(* Logix 5000 project; controller Test vendor 1 type 14 code 92 rev 32.11; software revision 32.00 *)

TASK MainTask (continuous, watchdog 500 ms) : MainProgram

MODULES
   Local : vendor 1 type 14 code 92 (ICP 0, rev 32.11)
      IN : vendor 1 type 7 code 1 (ICP 3, rev 3.2, Input RPI 20 ms)
      O : vendor 1 type 7 code 15 (ICP 2, rev 3.2, Output RPI 20 ms)
      Ethernet : 1756-ENBT (ICP 1, Ethernet 192.168.0.98, rev 6.4)
         SC10 : XS26 SC26 SC10 (Ethernet 192.168.0.128, rev 2.1, StandardDataDriven RPI 100 ms)
END_MODULES

TYPE Banner_Chain_Status_v1 :
STRUCT
   Device_Count_Mismatch : BOOL;   // 0 = False, 1 = True
   Device_Order_Mismatch : BOOL;   // 0 = False, 1 = True
   No_Diagnostics_Data_Detected : BOOL;   // 0 = False, 1 = True
   bit3 : BOOL;
   Incompatible_Device : BOOL;   // 0 = False, 1 = True
   ISD_Terminator_Missing : BOOL;   // 0 = False, 1 = True
   ISD_Actuator_Not_Taught : BOOL;   // 0 = False, 1 = True
   ISD_Wrong_Actuator : BOOL;   // 0 = False, 1 = True
   ISD_Internal_Error : BOOL;   // 0 = False, 1 = True
   ISD_Output_Fault_Detected : BOOL;   // 0 = False, 1 = True
   ISD_Chain_Change_Detected : BOOL;   // 0 = False, 1 = True
   bit11 : BOOL;
   ISD_OSSD_Status : BOOL;   // 0 = Off, 1 = ON
   bit13 : BOOL;
   bit14 : BOOL;
   bit15 : BOOL;
   bit16 : BOOL;
   bit17 : BOOL;
   bit18 : BOOL;
   bit19 : BOOL;
   bit20 : BOOL;
   bit21 : BOOL;
   bit22 : BOOL;
   bit23 : BOOL;
   bit24 : BOOL;
   bit25 : BOOL;
   bit26 : BOOL;
   bit27 : BOOL;
   bit28 : BOOL;
   bit29 : BOOL;
   bit30 : BOOL;
   bit31 : BOOL;
END_STRUCT
END_TYPE

TYPE Banner_ISD_Data_v1 :   // Tag Data for a Banner ISD Device.
STRUCT
   Safety_Input_Fault : SINT;   // System detected a fault on the safety input. Power cycle required. 1 = True, 0 = False.
   Reserved : SINT;
   Sensor_not_Paired : SINT;   // Si-RF Only. High or Unique sensor that has not been taught (not taught 1, taught 0)
   ISD_Data_Error : SINT;   // 1 = corrupted data was received by the Safety Controller, 0 = data ok.
   Wrong_Actuator : SINT;   // Si-RF sensor detects an actuator with a "received code" that does not match the "expected code" (wrong 1, correct 0).
   Marginal_Range : SINT;   // Si-RF Only. Actuator detected but is staying at the extreme end of detection range (13 to 15 mm away from sensor). 1 = True, 0 = False.
   Actuator_Detected : SINT;   // Si-RF sensor detects an actuator. Note: It does not have to be the taught actuator.
   Output_Error : SINT;   // ISD device detects an output short to voltage or ground. This starts the "switch-off timer" counter. 1= Error detected, 0 = OK.
   Input_1 : SINT;   // ISD device input 1 is on (1) or off (0)
   Input_2 : SINT;   // ISD device input 2 is on (1) or off (0)
   Local_Reset_Expected : SINT;   // An ISD device with latching feature requires a reset. 1 = reset needed. ISD Connect is always 0.
   Operating_Voltage_Warning : SINT;   // Voltage to the ISD device is at limit of specificaitons. 1 = at limit, 0 = OK.
   Operating_Voltage_Error : SINT;   // Voltage to the ISD device is above/over 30 Vdc or below/less 19.2 Vdc limit of range.
   Output_1 : SINT;   // 1 = Output On, 0 = Output Off
   Output_2 : SINT;   // 1 = Output On, 0 = Output Off
   Power_Cycle_Required : SINT;   // 1 = ISD device detects a fault. Power cycled required.
   Fault_Tolerant_Outputs : SINT;   // 1 = ISD device includes 20 minute off delay/fault delay. Always 1 for ISD E-Stop and ISD Connect.
   Local_Reset_Unit : SINT;   // 1 = ISD device includes the latch feature, 0 = device has the auto reset feature. Always 0 for ISD Connect.
   Cascadable : SINT;   // 1 = ISD device includes the cascade feature. Always 1 for ISD E-Stop and ISD Connect.
   High_Coding_Level : SINT;   // Si-RF Only. 1 = Device is High or Unique model, 0 = Low model.
   Teach_ins_Remaining : INT;   // Si-RF Only. Number of teaches remaining for Si-RF devices with high or unique coding.
   Device_Id : INT;   // ISD Device Type 1 = Si-RF. 7 for ISD E-Stop, 9 for ISD Connect.
   Range_Warning_Count : INT;   // Si-RF sensor only. Count of number of range warnings received in the last 60 minutes.
   Output_Switch_Out_Time : INT;   // Delay counter for certain output errors. 0 = inactive, 1 to 20 = remaining minutes to device lockout state. Value = 31 means Timer is Off.
   Number_of_Voltage_Errors : INT;   // 0 to 60 = Number of voltage warnings received in the last 60 seconds.
   Internal_Temperature : REAL;   // Internal temperature of device in Celsius.
   Actuator_Distance : REAL;   // The distance the actuator is from the Si-RF. Value displayed as a percentage of the Si-RF range.
   Supply_Voltage : REAL;   // Actual input voltage detected by the ISD sensor.
   Expected_Company_Name : INT;   // Fixed value of 6.
   Received_Company_Name : INT;   // Si-RF Only. Value received from Sensor. Should match Expected Company Name.
   Expected_Code : INT;   // Si-RF sensor with high or unique coding displays the actuator code taught to the sensor.
   Received_Code : INT;   // Displays actuator code detected by the Si-RF sensor.
   Internal_Error_A : DINT;
   Internal_Error_B : DINT;
END_STRUCT
END_TYPE

TYPE Banner_ISD_Devices_v1 :
STRUCT
   Device : SINT[32];   // 1 = ISD Si-RF switch, 7 = ISD E-Stop, 9 = ISD Connect
END_STRUCT
END_TYPE

TYPE Banner_ISD_Dual_Chain_Status_v1 :   // UDT that gives the overall Chain information for an ISD device.
STRUCT
   C1_Inputs : DINT;
   C2_Inputs : DINT;
   C1_On_Off : DINT;
   C2_On_Off : DINT;
   C1_Fault : DINT;
   C2_Fault : DINT;
   C1_Marginal : DINT;
   C2_Marginal : DINT;
   C1_Alert : DINT;
   C2_Alert : DINT;
   C1_Reset : DINT;
   C2_Reset : DINT;
   C1_Actuator_State : DINT;
   C2_Actuator_State : DINT;
   C1_Series_Status : Banner_Chain_Status_v1;
   C2_Series_Status : Banner_Chain_Status_v1;
END_STRUCT
END_TYPE

TYPE Banner_ISD_UDT_v1 :
STRUCT
   ISD_Request : INT;   // Set to 1 to start an ISD Request to the Safety Controller.
   ISD_Chain : INT;   // Set to a value of 1 to 2 for SC10, or 1 to 8 for XS26.
   ISD_Device : INT;   // Enter a value fo 1 to 32 to access that device during the ISD communications.
   ISD_Request_ACK : INT;   // Returns a value of when ISD request is successful.
   ISD_Chain_ACK : INT;   // Returns a 1 or 2 if communications with Chain is successful.
   ISD_Device_ACK : INT;   // Returns device value if communications is successful.
   Error : INT;   // Stores a numberical value representing an error condition.
   Data : Banner_ISD_Data_v1;   // Device Data for the current read.
   Devices : Banner_ISD_Devices_v1;
   Data_In : INT[12];   // Array to transfer raw data into AOI.
   Data_InList : INT[16];   // Array to transfer the raw data for list of devices. Only used with XS26.
   Data_Out : INT[3];   // Array to transfer raw data out of AOI.
   Data_Storage_Required : INT;   // Data storage required after last data read complete.
   Reset : INT;   // Reset the AOI.
END_STRUCT
END_TYPE

ADD_ON_INSTRUCTION Banner_ISD_v1   (* revision 1.0, vendor Banner Engineering *)
VAR_IN_OUT
   ISD : Banner_ISD_UDT_v1; {required}
END_VAR
VAR_INPUT
   Model : DINT; {required}
END_VAR
VAR
   Lock : DINT; {access None}
   Timer1 : TIMER := (PRE := 300); {access None}
   Timer2 : TIMER := (PRE := 1000); {access None}
   Device : DINT; {access None}   // ISD Device
   Chain : DINT; {access None}   // ISD Series
   Distance2 : DINT[13] := ([1] := 7, [2] := 8, [3] := 9, [4] := 10, [5] := 11, [6] := 12, [7] := 13, [8] := 14, [9] := 15, [10] := 16, [11] := 17, [12] := 18); {access None}
   Distance1 : DINT[13] := ([0] := 61, [1] := 62, [2] := 65, [3] := 77, [4] := 110, [5] := 133, [6] := 148, [7] := 158, [8] := 163, [9] := 169, [10] := 172, [11] := 176, [12] := 180); {access None}
   Temp2 : DINT[31]; {access None}
   Temp1 : DINT[31]; {access None}
   T_Distance : DINT; {access None}
   T_Temp : DINT; {access None}
   IndexD : DINT; {access None}
   IndexT : DINT; {access None}
   Shift_T : DINT; {access None}
   T_Voltage : DINT; {access None}
   LL : DINT; {access None}
   UL : DINT; {access None}
END_VAR

ROUTINE Logic   (* ladder *)
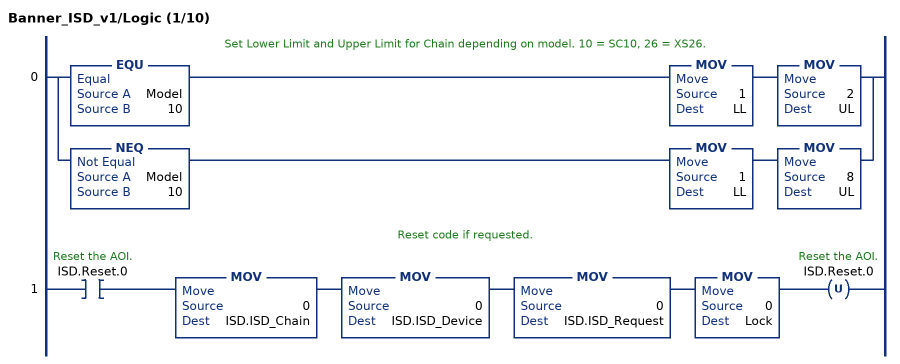
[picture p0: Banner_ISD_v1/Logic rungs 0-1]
   // Set Lower Limit and Upper Limit for Chain depending on model. 10 = SC10, 26 = XS26.
   0: [EQU(Model,10) MOV(1,LL) MOV(2,UL) ,NEQ(Model,10) MOV(1,LL) MOV(8,UL) ];
   // Reset code if requested.
   1: XIC(ISD.Reset.0)MOV(0,ISD.ISD_Chain)MOV(0,ISD.ISD_Device)MOV(0,ISD.ISD_Request)MOV(0,Lock)OTU(ISD.Reset.0);
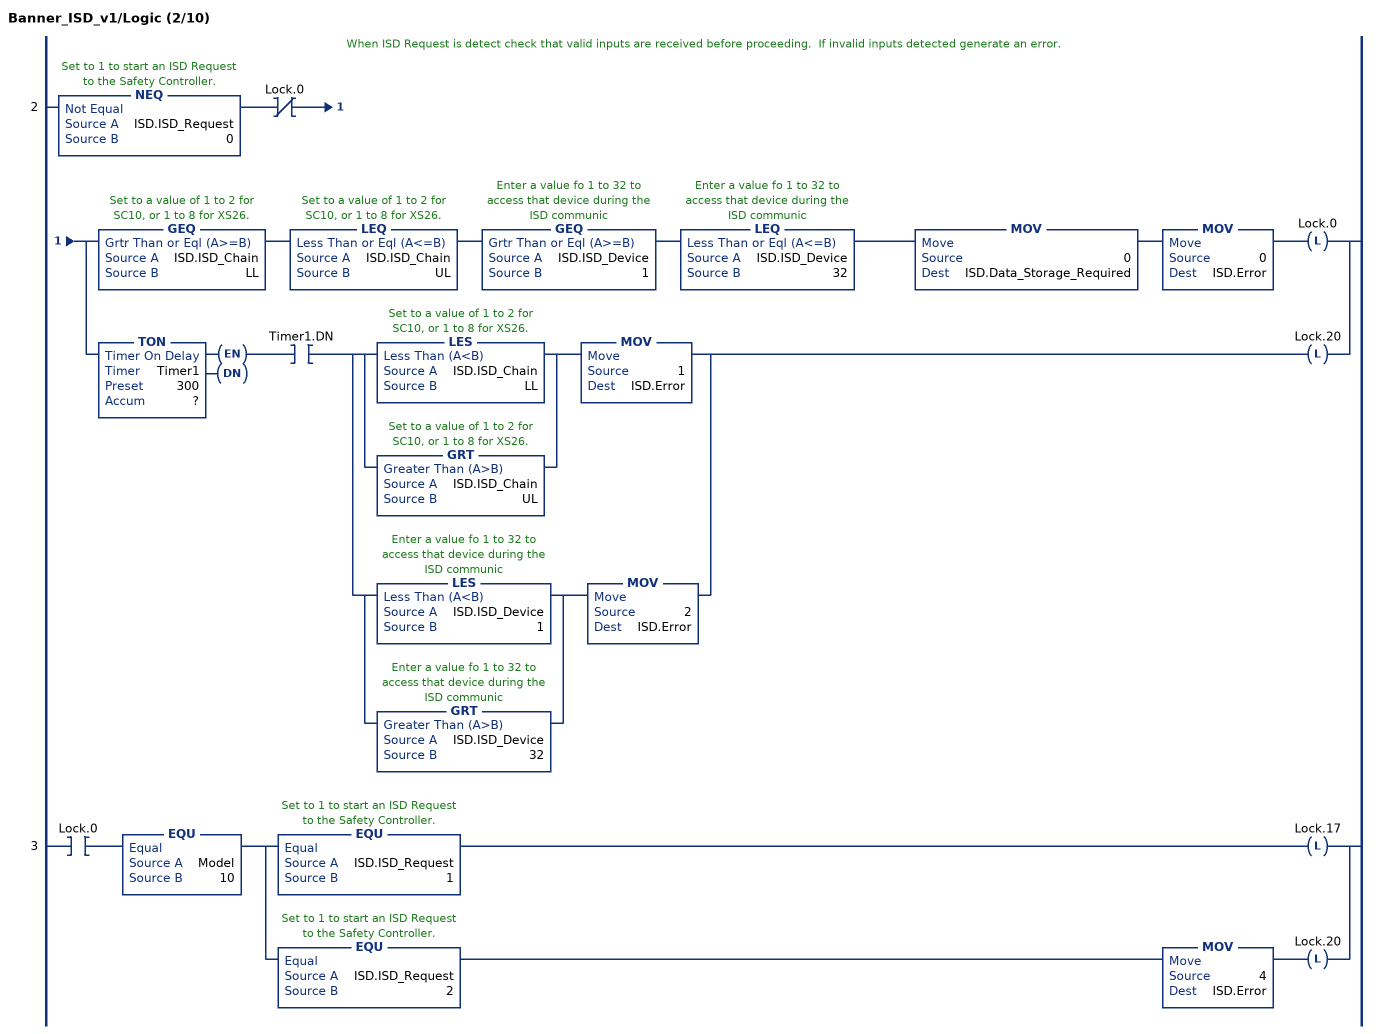
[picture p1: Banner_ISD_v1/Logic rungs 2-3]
   // When ISD Request is detect check that valid inputs are received before proceeding.  If invalid inputs detected generate an error.
   2: NEQ(ISD.ISD_Request,0)XIO(Lock.0)[GEQ(ISD.ISD_Chain,LL) LEQ(ISD.ISD_Chain,UL) GEQ(ISD.ISD_Device,1) LEQ(ISD.ISD_Device,32) MOV(0,ISD.Data_Storage_Required) MOV(0,ISD.Error) OTL(Lock.0) ,TON(Timer1,?,?) XIC(Timer1.DN) [[LES(ISD.ISD_Chain,LL) ,GRT(ISD.ISD_Chain,UL) ] MOV(1,ISD.Error) ,[LES(ISD.ISD_Device,1) ,GRT(ISD.ISD_Device,32) ] MOV(2,ISD.Error) ] OTL(Lock.20) ];
   3: XIC(Lock.0)EQU(Model,10)[EQU(ISD.ISD_Request,1) OTL(Lock.17) ,EQU(ISD.ISD_Request,2) MOV(4,ISD.Error) OTL(Lock.20) ];
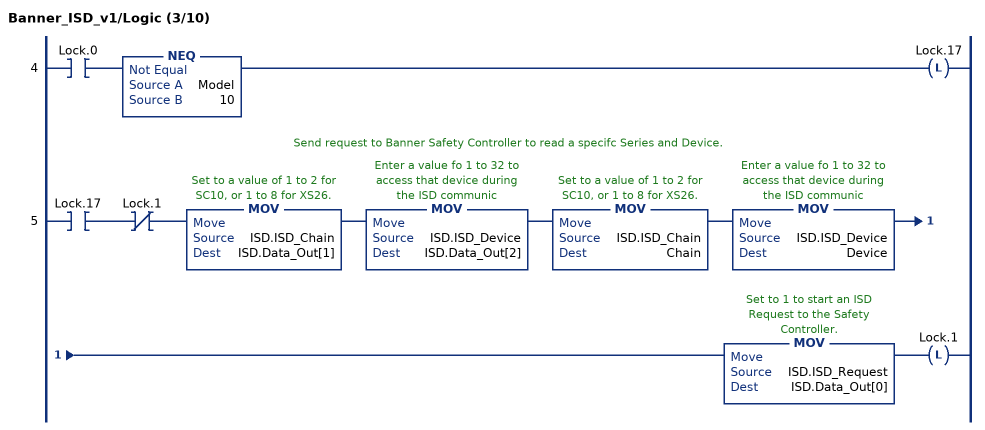
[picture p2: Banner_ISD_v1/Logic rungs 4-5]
   4: XIC(Lock.0)NEQ(Model,10)OTL(Lock.17);
   // Send request to Banner Safety Controller to read a specifc Series and Device.
   5: XIC(Lock.17)XIO(Lock.1)MOV(ISD.ISD_Chain,ISD.Data_Out[1])MOV(ISD.ISD_Device,ISD.Data_Out[2])MOV(ISD.ISD_Chain,Chain)MOV(ISD.ISD_Device,Device)MOV(ISD.ISD_Request,ISD.Data_Out[0])OTL(Lock.1);
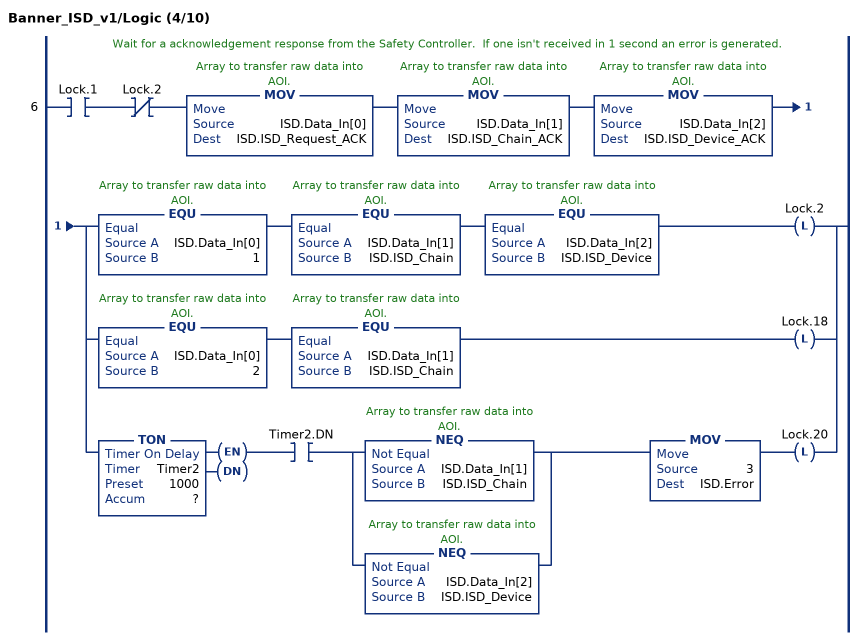
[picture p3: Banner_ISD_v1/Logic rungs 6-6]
   // Wait for a acknowledgement response from the Safety Controller.  If one isn't received in 1 second an error is generated.
   6: XIC(Lock.1)XIO(Lock.2)MOV(ISD.Data_In[0],ISD.ISD_Request_ACK)MOV(ISD.Data_In[1],ISD.ISD_Chain_ACK)MOV(ISD.Data_In[2],ISD.ISD_Device_ACK)[[EQU(ISD.Data_In[0],1) EQU(ISD.Data_In[1],ISD.ISD_Chain) EQU(ISD.Data_In[2],ISD.ISD_Device) OTL(Lock.2) ,EQU(ISD.Data_In[0],2) EQU(ISD.Data_In[1],ISD.ISD_Chain) OTL(Lock.18) ] ,TON(Timer2,?,?) XIC(Timer2.DN) [NEQ(ISD.Data_In[1],ISD.ISD_Chain) ,NEQ(ISD.Data_In[2],ISD.ISD_Device) ] MOV(3,ISD.Error) OTL(Lock.20) ];
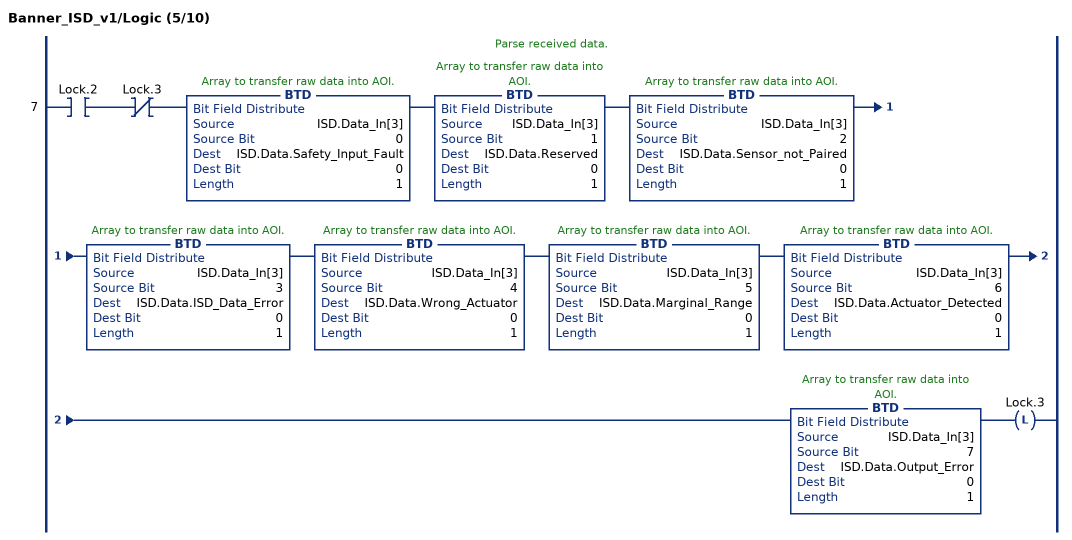
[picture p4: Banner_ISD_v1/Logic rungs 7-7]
   // Parse received data.
   7: XIC(Lock.2)XIO(Lock.3)BTD(ISD.Data_In[3],0,ISD.Data.Safety_Input_Fault,0,1)BTD(ISD.Data_In[3],1,ISD.Data.Reserved,0,1)BTD(ISD.Data_In[3],2,ISD.Data.Sensor_not_Paired,0,1)BTD(ISD.Data_In[3],3,ISD.Data.ISD_Data_Error,0,1)BTD(ISD.Data_In[3],4,ISD.Data.Wrong_Actuator,0,1)BTD(ISD.Data_In[3],5,ISD.Data.Marginal_Range,0,1)BTD(ISD.Data_In[3],6,ISD.Data.Actuator_Detected,0,1)BTD(ISD.Data_In[3],7,ISD.Data.Output_Error,0,1)OTL(Lock.3);
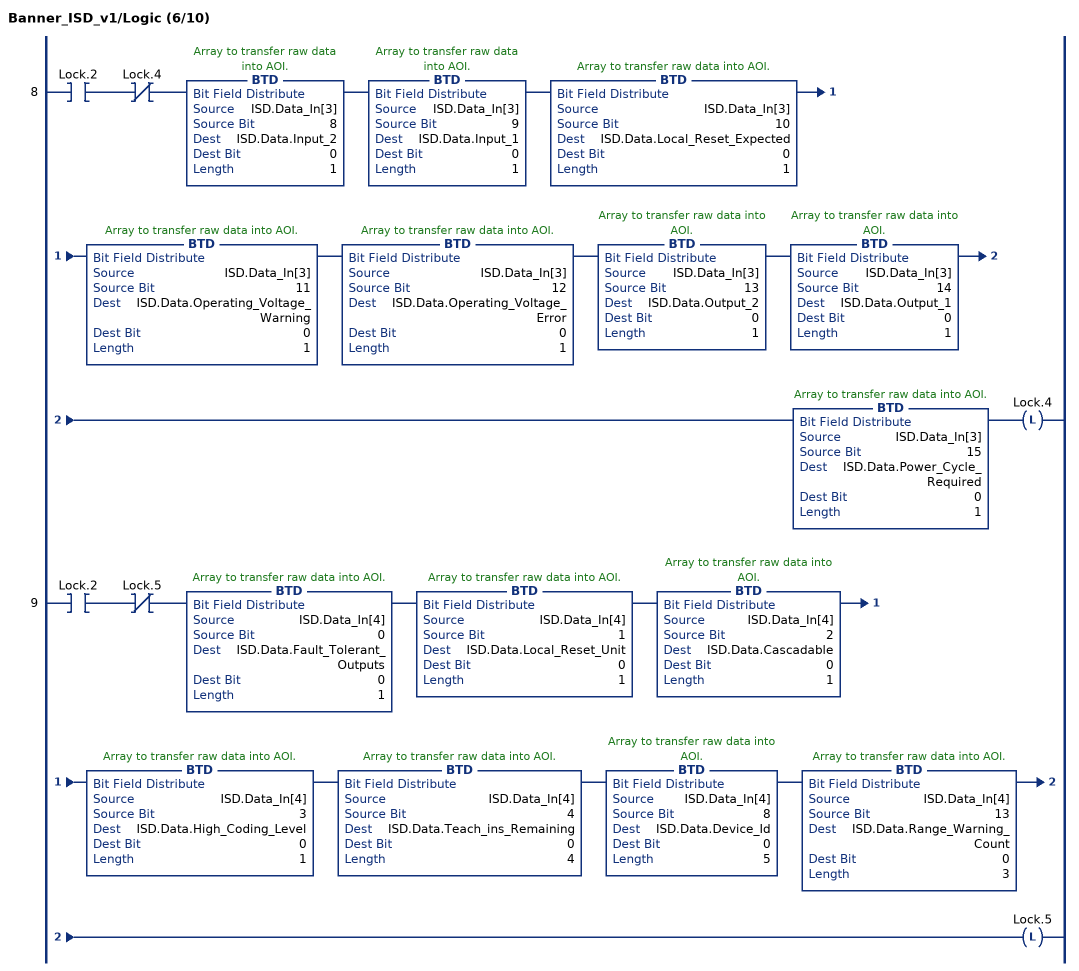
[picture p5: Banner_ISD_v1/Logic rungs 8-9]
   8: XIC(Lock.2)XIO(Lock.4)BTD(ISD.Data_In[3],8,ISD.Data.Input_2,0,1)BTD(ISD.Data_In[3],9,ISD.Data.Input_1,0,1)BTD(ISD.Data_In[3],10,ISD.Data.Local_Reset_Expected,0,1)BTD(ISD.Data_In[3],11,ISD.Data.Operating_Voltage_Warning,0,1)BTD(ISD.Data_In[3],12,ISD.Data.Operating_Voltage_Error,0,1)BTD(ISD.Data_In[3],13,ISD.Data.Output_2,0,1)BTD(ISD.Data_In[3],14,ISD.Data.Output_1,0,1)BTD(ISD.Data_In[3],15,ISD.Data.Power_Cycle_Required,0,1)OTL(Lock.4);
   9: XIC(Lock.2)XIO(Lock.5)BTD(ISD.Data_In[4],0,ISD.Data.Fault_Tolerant_Outputs,0,1)BTD(ISD.Data_In[4],1,ISD.Data.Local_Reset_Unit,0,1)BTD(ISD.Data_In[4],2,ISD.Data.Cascadable,0,1)BTD(ISD.Data_In[4],3,ISD.Data.High_Coding_Level,0,1)BTD(ISD.Data_In[4],4,ISD.Data.Teach_ins_Remaining,0,4)BTD(ISD.Data_In[4],8,ISD.Data.Device_Id,0,5)BTD(ISD.Data_In[4],13,ISD.Data.Range_Warning_Count,0,3)OTL(Lock.5);
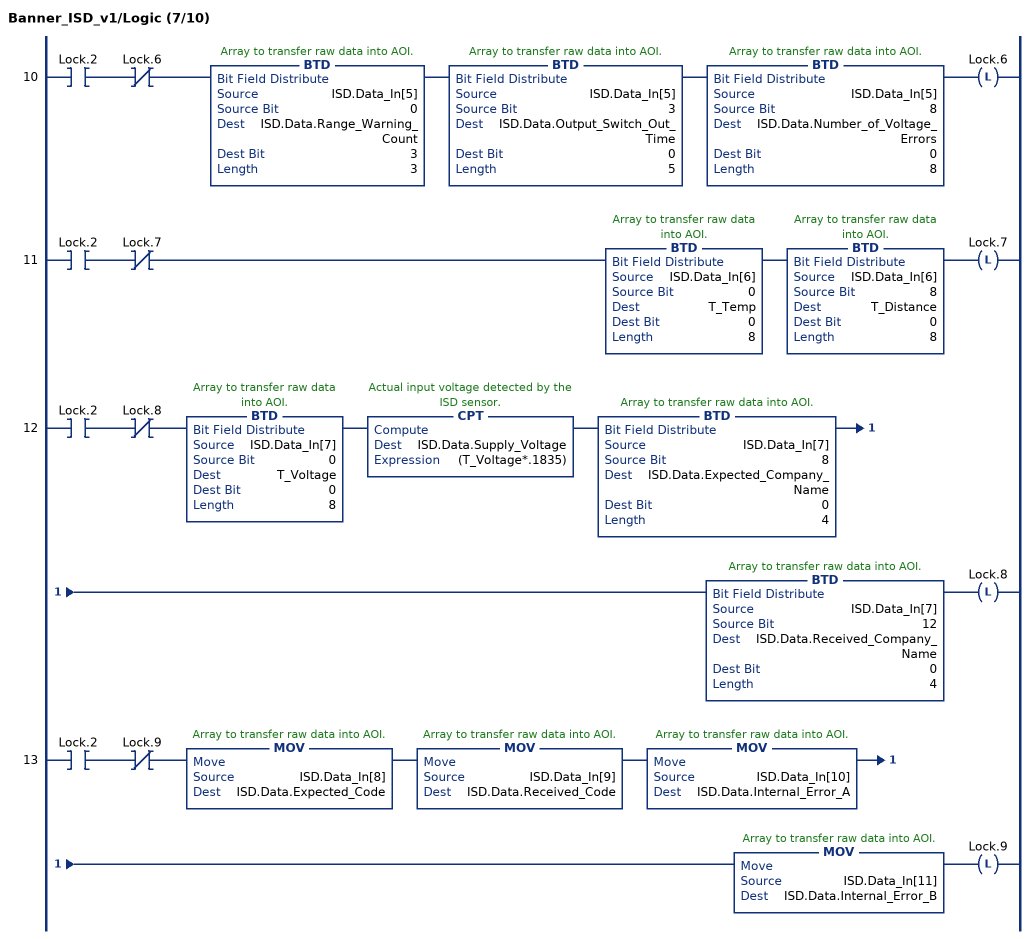
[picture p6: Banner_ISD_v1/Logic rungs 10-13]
   10: XIC(Lock.2)XIO(Lock.6)BTD(ISD.Data_In[5],0,ISD.Data.Range_Warning_Count,3,3)BTD(ISD.Data_In[5],3,ISD.Data.Output_Switch_Out_Time,0,5)BTD(ISD.Data_In[5],8,ISD.Data.Number_of_Voltage_Errors,0,8)OTL(Lock.6);
   11: XIC(Lock.2)XIO(Lock.7)BTD(ISD.Data_In[6],0,T_Temp,0,8)BTD(ISD.Data_In[6],8,T_Distance,0,8)OTL(Lock.7);
   12: XIC(Lock.2)XIO(Lock.8)BTD(ISD.Data_In[7],0,T_Voltage,0,8)CPT(ISD.Data.Supply_Voltage,(T_Voltage*.1835))BTD(ISD.Data_In[7],8,ISD.Data.Expected_Company_Name,0,4)BTD(ISD.Data_In[7],12,ISD.Data.Received_Company_Name,0,4)OTL(Lock.8);
   13: XIC(Lock.2)XIO(Lock.9)MOV(ISD.Data_In[8],ISD.Data.Expected_Code)MOV(ISD.Data_In[9],ISD.Data.Received_Code)MOV(ISD.Data_In[10],ISD.Data.Internal_Error_A)MOV(ISD.Data_In[11],ISD.Data.Internal_Error_B)OTL(Lock.9);
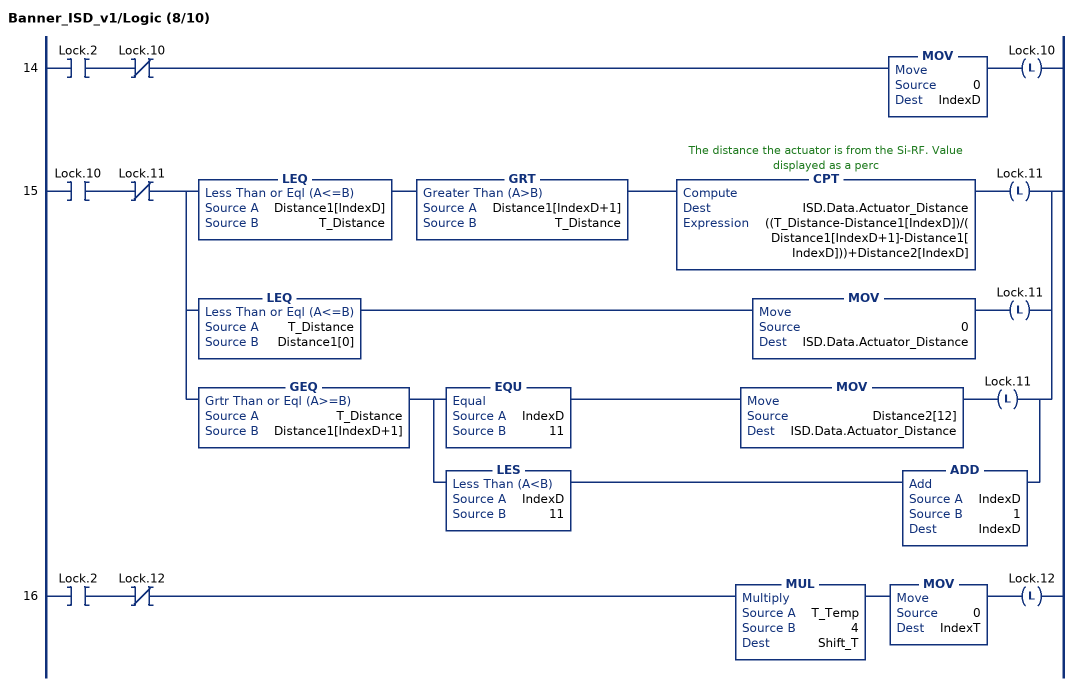
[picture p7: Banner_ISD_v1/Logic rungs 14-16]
   14: XIC(Lock.2)XIO(Lock.10)MOV(0,IndexD)OTL(Lock.10);
   15: XIC(Lock.10)XIO(Lock.11)[LEQ(Distance1[IndexD],T_Distance) GRT(Distance1[IndexD+1],T_Distance) CPT(ISD.Data.Actuator_Distance,((T_Distance-Distance1[IndexD])/(Distance1[IndexD+1]-Distance1[IndexD]))+Distance2[IndexD]) OTL(Lock.11) ,[LEQ(T_Distance,Distance1[0]) MOV(0,ISD.Data.Actuator_Distance) OTL(Lock.11) ,GEQ(T_Distance,Distance1[IndexD+1]) [EQU(IndexD,11) MOV(Distance2[12],ISD.Data.Actuator_Distance) OTL(Lock.11) ,LES(IndexD,11) ADD(IndexD,1,IndexD) ] ] ];
   16: XIC(Lock.2)XIO(Lock.12)MUL(T_Temp,4,Shift_T)MOV(0,IndexT)OTL(Lock.12);
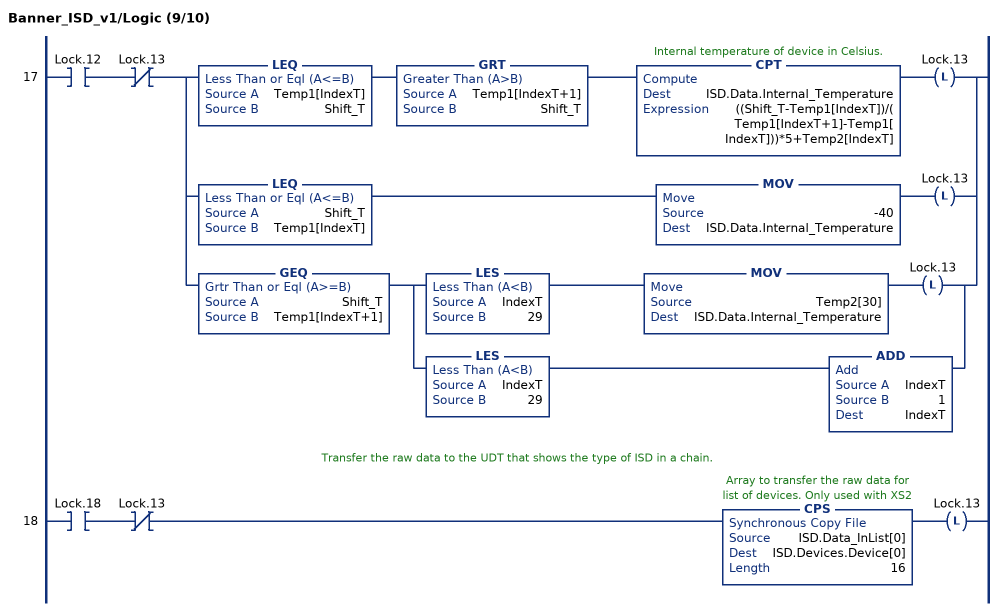
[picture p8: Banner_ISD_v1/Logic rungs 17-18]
   17: XIC(Lock.12)XIO(Lock.13)[LEQ(Temp1[IndexT],Shift_T) GRT(Temp1[IndexT+1],Shift_T) CPT(ISD.Data.Internal_Temperature,((Shift_T-Temp1[IndexT])/(Temp1[IndexT+1]-Temp1[IndexT]))*5+Temp2[IndexT]) OTL(Lock.13) ,[LEQ(Shift_T,Temp1[IndexT]) MOV(-40,ISD.Data.Internal_Temperature) OTL(Lock.13) ,GEQ(Shift_T,Temp1[IndexT+1]) [LES(IndexT,29) MOV(Temp2[30],ISD.Data.Internal_Temperature) OTL(Lock.13) ,LES(IndexT,29) ADD(IndexT,1,IndexT) ] ] ];
   // Transfer the raw data to the UDT that shows the type of ISD in a chain.
   18: XIC(Lock.18)XIO(Lock.13)CPS(ISD.Data_InList[0],ISD.Devices.Device[0],16)OTL(Lock.13);
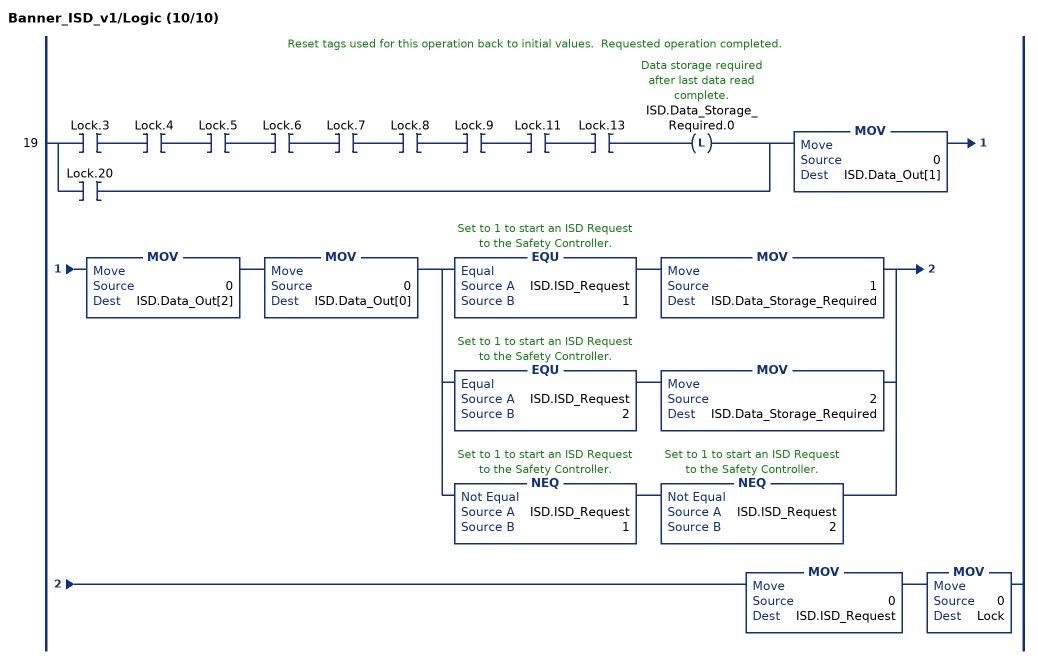
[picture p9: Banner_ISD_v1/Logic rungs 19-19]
   // Reset tags used for this operation back to initial values.  Requested operation completed.
   19: [XIC(Lock.3) XIC(Lock.4) XIC(Lock.5) XIC(Lock.6) XIC(Lock.7) XIC(Lock.8) XIC(Lock.9) XIC(Lock.11) XIC(Lock.13) OTL(ISD.Data_Storage_Required.0) ,XIC(Lock.20) ]MOV(0,ISD.Data_Out[1])MOV(0,ISD.Data_Out[2])MOV(0,ISD.Data_Out[0])[EQU(ISD.ISD_Request,1) MOV(1,ISD.Data_Storage_Required) ,EQU(ISD.ISD_Request,2) MOV(2,ISD.Data_Storage_Required) ,NEQ(ISD.ISD_Request,1) NEQ(ISD.ISD_Request,2) ]MOV(0,ISD.ISD_Request)MOV(0,Lock);
END_ROUTINE
END_ADD_ON_INSTRUCTION

VAR_GLOBAL   (* controller tags *)
   SC10_ISD_01 : Banner_ISD_UDT_v1;
   SC10_ISD_01_Status : Banner_ISD_v1;
   SC10_ISD_Devices : Banner_ISD_Dual_Chain_Status_v1;
END_VAR

PROGRAM MainProgram   (* main routine MainRoutine *)

ROUTINE MainRoutine   (* ladder *)
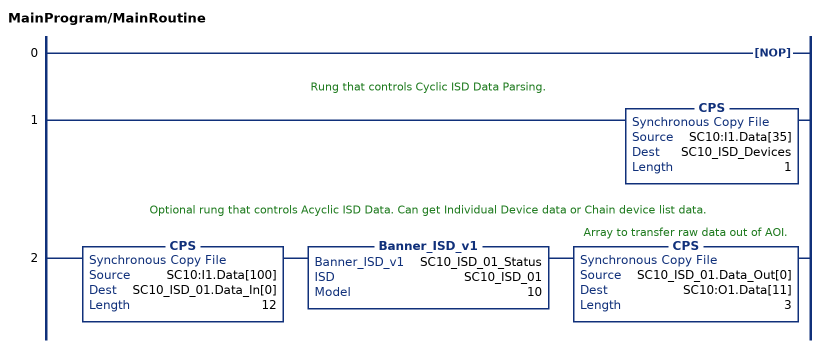
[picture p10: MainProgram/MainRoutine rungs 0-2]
   0: NOP();
   // Rung that controls Cyclic ISD Data Parsing.
   1: CPS(SC10:I1.Data[35],SC10_ISD_Devices,1);
   // Optional rung that controls Acyclic ISD Data. Can get Individual Device data or Chain device list data.
   2: CPS(SC10:I1.Data[100],SC10_ISD_01.Data_In[0],12)Banner_ISD_v1(SC10_ISD_01_Status,SC10_ISD_01,10)CPS(SC10_ISD_01.Data_Out[0],SC10:O1.Data[11],3);
END_ROUTINE
END_PROGRAM
